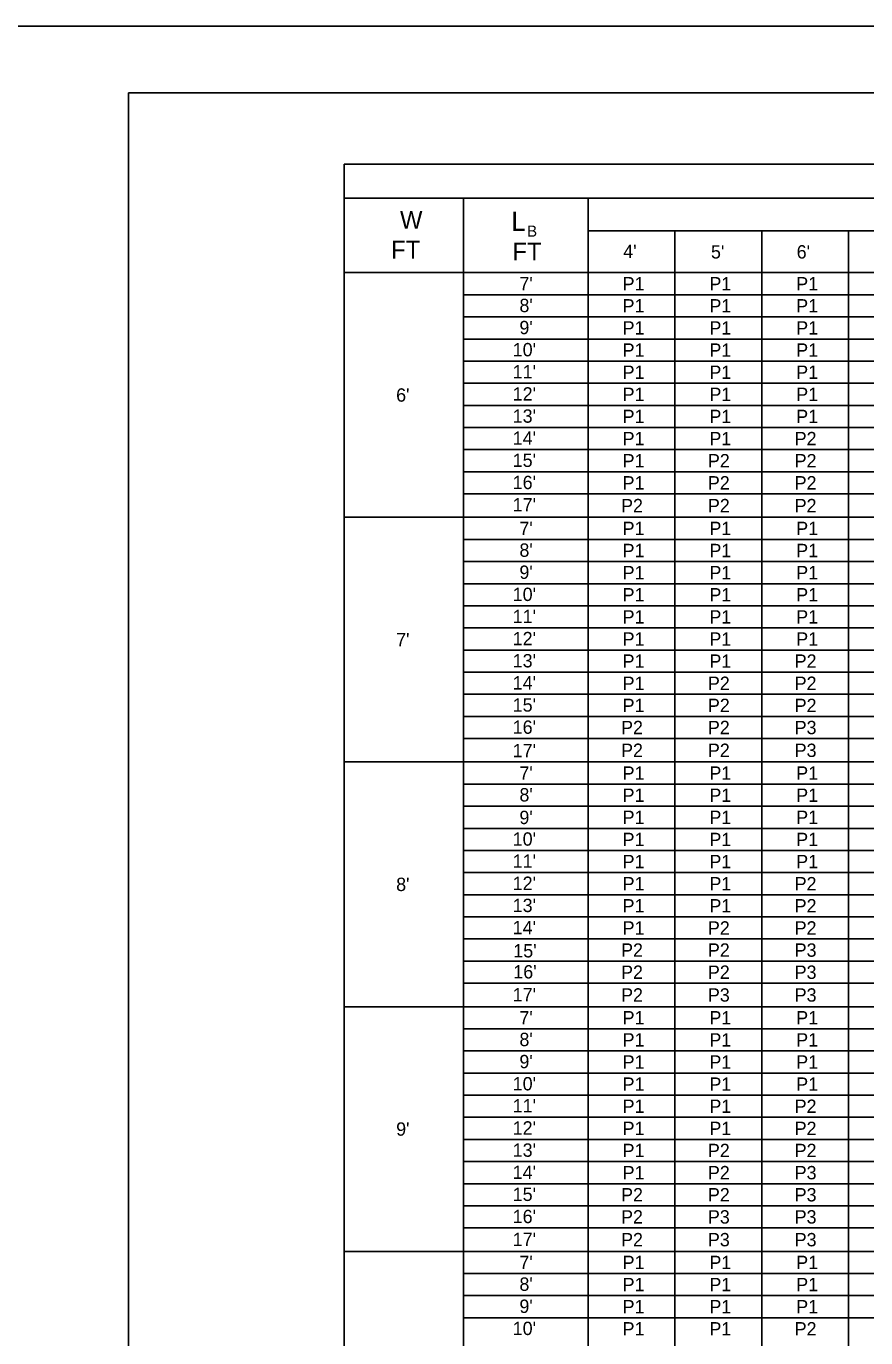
# Model space of a CAD drawing. Extents: x 637580 to 641008, y 294594 to 295782.
# Drawn here: x 638438.3 to 638627, y 295486.9 to 295781.6 of the extents above; entities that cross this region are included whole.
import ezdxf

# ---------------------------------------------------------------- set-up
doc = ezdxf.new("R2010")
doc.units = 0
for name, color, linetype in [('1', 7, 'Continuous'), ('2', 7, 'Continuous'), ('PLT-BNDY', 7, 'Continuous')]:
    doc.layers.add(name, color=color, linetype=linetype)

msp = doc.modelspace()

# ---------------------------------------------------------------- linework, layer by layer
at = {"layer": '1'}
for p, q in [((638461.31, 295766.63), (639247.31, 295766.63)), ((638461.31, 295766.63), (638461.31, 295202.63)), ((638509.81, 295750.63), (638876.73, 295750.63)), ((638509.81, 295231.34), (638509.81, 295750.63)), ((638509.81, 295742.95), (638876.73, 295742.95)), ((638536.61, 295231.34), (638536.61, 295742.95)), ((638564.61, 295231.34), (638564.61, 295742.95)), ((638584.12, 295231.34), (638584.12, 295735.61)), ((638603.63, 295231.34), (638603.63, 295735.61)), ((638623.14, 295231.34), (638623.14, 295735.61)), ((638509.81, 295726.25), (638876.73, 295726.25)), ((638509.81, 295671.26), (638876.73, 295671.26)), ((638509.81, 295616.27), (638876.73, 295616.27)), ((638509.81, 295561.28), (638876.73, 295561.28)), ((638509.81, 295506.29), (638876.73, 295506.29))]:
    msp.add_line(p, q, dxfattribs=at)
at = {"layer": '2'}
for p, q in [((638564.61, 295735.61), (638876.73, 295735.61)), ((638536.61, 295721.27), (638876.73, 295721.27)), ((638536.61, 295716.3), (638876.73, 295716.3)), ((638536.61, 295711.33), (638876.73, 295711.33)), ((638536.61, 295706.36), (638876.73, 295706.36)), ((638536.61, 295701.39), (638876.73, 295701.39)), ((638536.61, 295696.41), (638876.73, 295696.41)), ((638536.61, 295691.44), (638876.73, 295691.44)), ((638536.61, 295686.47), (638876.73, 295686.47)), ((638536.61, 295681.5), (638876.73, 295681.5)), ((638536.61, 295676.52), (638876.73, 295676.52)), ((638536.61, 295666.29), (638876.73, 295666.29)), ((638536.61, 295661.31), (638876.73, 295661.31)), ((638536.61, 295656.34), (638876.73, 295656.34)), ((638536.61, 295651.37), (638876.73, 295651.37)), ((638536.61, 295646.4), (638876.73, 295646.4)), ((638536.61, 295641.42), (638876.73, 295641.42)), ((638536.61, 295636.45), (638876.73, 295636.45)), ((638536.61, 295631.48), (638876.73, 295631.48)), ((638536.61, 295626.51), (638876.73, 295626.51)), ((638536.61, 295621.53), (638876.73, 295621.53)), ((638536.61, 295611.3), (638876.73, 295611.3)), ((638536.61, 295606.32), (638876.73, 295606.32)), ((638536.61, 295601.35), (638876.73, 295601.35)), ((638536.61, 295596.38), (638876.73, 295596.38)), ((638536.61, 295591.41), (638876.73, 295591.41)), ((638536.61, 295586.43), (638876.73, 295586.43)), ((638536.61, 295581.46), (638876.73, 295581.46)), ((638536.61, 295576.49), (638876.73, 295576.49)), ((638536.61, 295571.52), (638876.73, 295571.52)), ((638536.61, 295566.54), (638876.73, 295566.54)), ((638536.61, 295556.31), (638876.73, 295556.31)), ((638536.61, 295551.33), (638876.73, 295551.33)), ((638536.61, 295546.36), (638876.73, 295546.36)), ((638536.61, 295541.39), (638876.73, 295541.39)), ((638536.61, 295536.42), (638876.73, 295536.42)), ((638536.61, 295531.44), (638876.73, 295531.44)), ((638536.61, 295526.47), (638876.73, 295526.47)), ((638536.61, 295521.5), (638876.73, 295521.5)), ((638536.61, 295516.53), (638876.73, 295516.53)), ((638536.61, 295511.55), (638876.73, 295511.55)), ((638536.61, 295501.32), (638876.73, 295501.32)), ((638536.61, 295496.34), (638876.73, 295496.34)), ((638536.61, 295491.37), (638876.73, 295491.37))]:
    msp.add_line(p, q, dxfattribs=at)
at = {"layer": 'PLT-BNDY'}
msp.add_lwpolyline([(638421.31, 295781.63), (639262.31, 295781.63), (639262.31, 295187.63), (638421.31, 295187.63)], close=True, dxfattribs=at)

# ---------------------------------------------------------------- texts
at = {"layer": '1'}
for s, height, p in [('W', 4, (638522.33, 295736.12)), ('L', 4.3, (638547.36, 295735.64)), ('B', 2.5, (638550.91, 295734.33)), ('FT', 4.003, (638520.34, 295729.41)), ('FT', 4.003, (638547.61, 295729.01)), ("4'", 3, (638572.5, 295729.52)), ("5'", 3, (638592.22, 295729.42)), ("6'", 3, (638611.48, 295729.42)), ("7'", 3, (638549.17, 295722.26)), ('P1', 3, (638572.36, 295722.26)), ('P1', 3, (638591.87, 295722.26)), ('P1', 3, (638611.38, 295722.26)), ("8'", 3, (638549.17, 295717.38)), ('P1', 3, (638572.36, 295717.29)), ('P1', 3, (638591.87, 295717.29)), ('P1', 3, (638611.38, 295717.29)), ("9'", 3, (638549.17, 295712.41)), ('P1', 3, (638572.36, 295712.32)), ('P1', 3, (638591.87, 295712.32)), ('P1', 3, (638611.38, 295712.32)), ("10'", 3, (638547.67, 295707.44)), ('P1', 3, (638572.36, 295707.34)), ('P1', 3, (638591.87, 295707.34)), ('P1', 3, (638611.38, 295707.34)), ("11'", 3, (638547.67, 295702.47)), ('P1', 3, (638572.36, 295702.37)), ('P1', 3, (638591.87, 295702.37)), ('P1', 3, (638611.38, 295702.37)), ("6'", 3, (638521.47, 295697.25)), ("12'", 3, (638547.67, 295697.49)), ('P1', 3, (638572.36, 295697.4)), ('P1', 3, (638591.87, 295697.4)), ('P1', 3, (638611.38, 295697.4)), ("13'", 3, (638547.67, 295692.52)), ('P1', 3, (638572.36, 295692.43)), ('P1', 3, (638591.87, 295692.43)), ('P1', 3, (638611.38, 295692.43)), ("14'", 3, (638547.67, 295687.55)), ('P1', 3, (638572.36, 295687.45)), ('P1', 3, (638591.87, 295687.45)), ('P2', 3, (638611.03, 295687.45)), ("15'", 3, (638547.67, 295682.58)), ('P1', 3, (638572.36, 295682.48)), ('P2', 3, (638591.53, 295682.48)), ('P2', 3, (638611.03, 295682.48)), ("16'", 3, (638547.67, 295677.6)), ('P1', 3, (638572.36, 295677.51)), ('P2', 3, (638591.53, 295677.51)), ('P2', 3, (638611.03, 295677.51)), ("17'", 3, (638547.67, 295672.58)), ('P2', 3, (638572.02, 295672.39)), ('P2', 3, (638591.53, 295672.39)), ('P2', 3, (638611.03, 295672.39)), ("7'", 3, (638549.17, 295667.27)), ('P1', 3, (638572.36, 295667.27)), ('P1', 3, (638591.87, 295667.27)), ('P1', 3, (638611.38, 295667.27)), ("8'", 3, (638549.17, 295662.39)), ('P1', 3, (638572.36, 295662.3)), ('P1', 3, (638591.87, 295662.3)), ('P1', 3, (638611.38, 295662.3)), ("9'", 3, (638549.17, 295657.42)), ('P1', 3, (638572.36, 295657.33)), ('P1', 3, (638591.87, 295657.33)), ('P1', 3, (638611.38, 295657.33)), ("10'", 3, (638547.67, 295652.45)), ('P1', 3, (638572.36, 295652.35)), ('P1', 3, (638591.87, 295652.35)), ('P1', 3, (638611.38, 295652.35)), ("11'", 3, (638547.67, 295647.48)), ('P1', 3, (638572.36, 295647.38)), ('P1', 3, (638591.87, 295647.38)), ('P1', 3, (638611.38, 295647.38)), ("7'", 3, (638521.47, 295642.26)), ("12'", 3, (638547.67, 295642.5)), ('P1', 3, (638572.36, 295642.41)), ('P1', 3, (638591.87, 295642.41)), ('P1', 3, (638611.38, 295642.41)), ("13'", 3, (638547.67, 295637.53)), ('P1', 3, (638572.36, 295637.44)), ('P1', 3, (638591.87, 295637.44)), ('P2', 3, (638611.03, 295637.44)), ("14'", 3, (638547.67, 295632.56)), ('P1', 3, (638572.36, 295632.46)), ('P2', 3, (638591.53, 295632.46)), ('P2', 3, (638611.03, 295632.46)), ("15'", 3, (638547.67, 295627.59)), ('P1', 3, (638572.36, 295627.49)), ('P2', 3, (638591.53, 295627.49)), ('P2', 3, (638611.03, 295627.49)), ("16'", 3, (638547.67, 295622.61)), ('P2', 3, (638572.02, 295622.52)), ('P2', 3, (638591.53, 295622.52)), ('P3', 3, (638611.03, 295622.52)), ("17'", 3, (638547.67, 295617.34)), ('P2', 3, (638572.02, 295617.4)), ('P2', 3, (638591.53, 295617.4)), ('P3', 3, (638611.03, 295617.4)), ("7'", 3, (638549.17, 295612.28)), ('P1', 3, (638572.36, 295612.28)), ('P1', 3, (638591.87, 295612.28)), ('P1', 3, (638611.38, 295612.28)), ("8'", 3, (638549.17, 295607.4)), ('P1', 3, (638572.36, 295607.31)), ('P1', 3, (638591.87, 295607.31)), ('P1', 3, (638611.38, 295607.31)), ("9'", 3, (638549.17, 295602.31)), ('P1', 3, (638572.36, 295602.34)), ('P1', 3, (638591.87, 295602.34)), ('P1', 3, (638611.38, 295602.34)), ("10'", 3, (638547.67, 295597.46)), ('P1', 3, (638572.36, 295597.36)), ('P1', 3, (638591.87, 295597.36)), ('P1', 3, (638611.38, 295597.36)), ("11'", 3, (638547.67, 295592.49)), ('P1', 3, (638572.36, 295592.39)), ('P1', 3, (638591.87, 295592.39)), ('P1', 3, (638611.38, 295592.39)), ("8'", 3, (638521.47, 295587.27)), ("12'", 3, (638547.67, 295587.51)), ('P1', 3, (638572.36, 295587.42)), ('P1', 3, (638591.87, 295587.42)), ('P2', 3, (638611.03, 295587.42)), ("13'", 3, (638547.67, 295582.54)), ('P1', 3, (638572.36, 295582.45)), ('P1', 3, (638591.87, 295582.45)), ('P2', 3, (638611.03, 295582.45)), ("14'", 3, (638547.67, 295577.57)), ('P1', 3, (638572.36, 295577.47)), ('P2', 3, (638591.53, 295577.47)), ('P2', 3, (638611.03, 295577.47)), ("15'", 3, (638547.8, 295572.35)), ('P2', 3, (638572.02, 295572.5)), ('P2', 3, (638591.53, 295572.5)), ('P3', 3, (638611.03, 295572.5)), ("16'", 3, (638547.8, 295567.62)), ('P2', 3, (638572.02, 295567.53)), ('P2', 3, (638591.53, 295567.53)), ('P3', 3, (638611.03, 295567.53)), ("17'", 3, (638547.67, 295562.47)), ('P2', 3, (638572.02, 295562.41)), ('P3', 3, (638591.53, 295562.41)), ('P3', 3, (638611.03, 295562.41)), ("7'", 3, (638549.17, 295557.29)), ('P1', 3, (638572.36, 295557.29)), ('P1', 3, (638591.87, 295557.29)), ('P1', 3, (638611.38, 295557.29)), ("8'", 3, (638549.17, 295552.41)), ('P1', 3, (638572.36, 295552.32)), ('P1', 3, (638591.87, 295552.32)), ('P1', 3, (638611.38, 295552.32)), ("9'", 3, (638549.17, 295547.44)), ('P1', 3, (638572.36, 295547.35)), ('P1', 3, (638591.87, 295547.35)), ('P1', 3, (638611.38, 295547.35)), ("10'", 3, (638547.67, 295542.47)), ('P1', 3, (638572.36, 295542.37)), ('P1', 3, (638591.87, 295542.37)), ('P1', 3, (638611.38, 295542.37)), ("11'", 3, (638547.67, 295537.5)), ('P1', 3, (638572.36, 295537.4)), ('P1', 3, (638591.87, 295537.4)), ('P2', 3, (638611.03, 295537.4)), ("9'", 3, (638521.47, 295532.28)), ("12'", 3, (638547.67, 295532.52)), ('P1', 3, (638572.36, 295532.43)), ('P1', 3, (638591.87, 295532.43)), ('P2', 3, (638611.03, 295532.43)), ("13'", 3, (638547.67, 295527.55)), ('P1', 3, (638572.36, 295527.46)), ('P2', 3, (638591.53, 295527.46)), ('P2', 3, (638611.03, 295527.46)), ("14'", 3, (638547.67, 295522.58)), ('P1', 3, (638572.36, 295522.48)), ('P2', 3, (638591.53, 295522.48)), ('P3', 3, (638611.03, 295522.48)), ("15'", 3, (638547.67, 295517.61)), ('P2', 3, (638572.02, 295517.51)), ('P2', 3, (638591.53, 295517.51)), ('P3', 3, (638611.03, 295517.51)), ("16'", 3, (638547.67, 295512.63)), ('P2', 3, (638572.02, 295512.54)), ('P3', 3, (638591.53, 295512.54)), ('P3', 3, (638611.03, 295512.54)), ("17'", 3, (638547.67, 295507.48)), ('P2', 3, (638572.02, 295507.42)), ('P3', 3, (638591.53, 295507.42)), ('P3', 3, (638611.03, 295507.42)), ("7'", 3, (638549.17, 295502.3)), ('P1', 3, (638572.36, 295502.3)), ('P1', 3, (638591.87, 295502.3)), ('P1', 3, (638611.38, 295502.3)), ("8'", 3, (638549.17, 295497.42)), ('P1', 3, (638572.36, 295497.33)), ('P1', 3, (638591.87, 295497.33)), ('P1', 3, (638611.38, 295497.33)), ("9'", 3, (638549.17, 295492.45)), ('P1', 3, (638572.36, 295492.36)), ('P1', 3, (638591.87, 295492.36)), ('P1', 3, (638611.38, 295492.36)), ("10'", 3, (638547.67, 295487.48)), ('P1', 3, (638572.36, 295487.38)), ('P1', 3, (638591.87, 295487.38)), ('P2', 3, (638611.03, 295487.38))]:
    msp.add_text(s, height=height, dxfattribs=at).set_placement(p)

doc.saveas('drawing.dxf')
